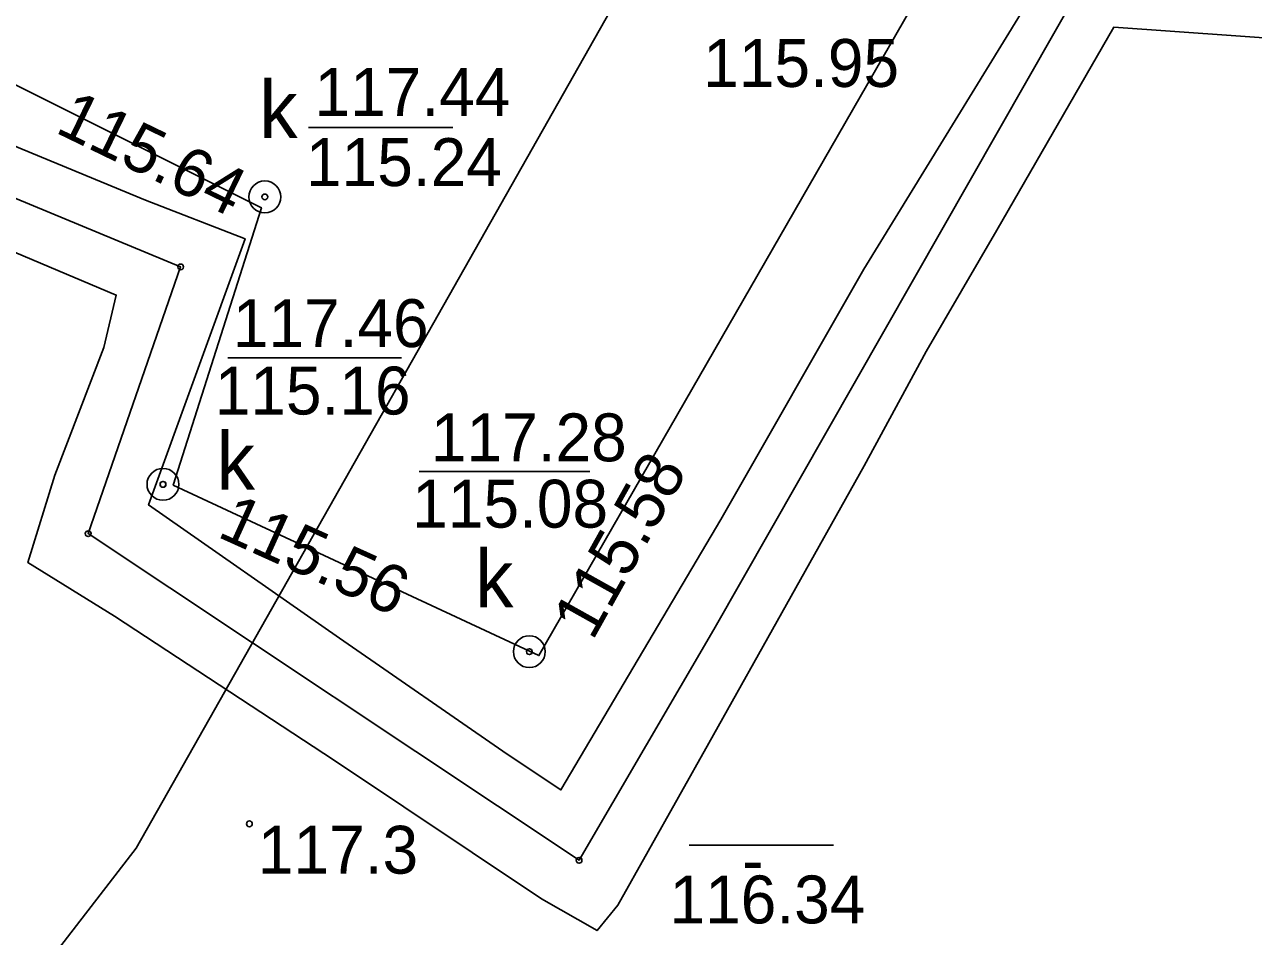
# Model space of a CAD drawing. Extents: x 6434771 to 6436222, y 5663454 to 5664782.
# Drawn here: x 6435606.44 to 6435625.69, y 5663645.64 to 5663659.92 of the extents above; entities that cross this region are included whole.
import ezdxf

# ---------------------------------------------------------------- set-up
doc = ezdxf.new("R2010")
doc.units = 0
for name, color, linetype in [('Warstwa 12', 7, 'Continuous'), ('Warstwa 13', 7, 'Continuous'), ('Warstwa 14', 7, 'Continuous'), ('Warstwa 4', 7, 'Continuous'), ('Warstwa 5', 7, 'Continuous'), ('Warstwa 6', 7, 'Continuous'), ('Warstwa 7', 7, 'Continuous'), ('Warstwa 8', 7, 'Continuous')]:
    doc.layers.add(name, color=color, linetype=linetype)

msp = doc.modelspace()

# ---------------------------------------------------------------- linework, layer by layer
at = {"layer": 'Warstwa 12'}
for points in [[(6435536.288, 5663690.931), (6435537.172, 5663690.476), (6435546.174, 5663686.087), (6435560.885, 5663678.992), (6435558.328, 5663673.766), (6435568.133, 5663668.92), (6435571.279, 5663674.37), (6435579.356, 5663669.847), (6435581.411, 5663668.891), (6435583.323, 5663667.758), (6435587.841, 5663665.584), (6435593.727, 5663662.778), (6435599.053, 5663660.202), (6435608.884, 5663656.122), (6435607.435, 5663651.945), (6435615.124, 5663646.829), (6435617.232, 5663650.442), (6435623.025, 5663660.599), (6435627.209, 5663660.193), (6435635.46, 5663657.931), (6435659.136, 5663652.875), (6435674.047, 5663650.076)], [(6435616.649, 5663663.165), (6435616.261, 5663661.285), (6435608.187, 5663647.021), (6435597.641, 5663633.357), (6435587.173, 5663617.963), (6435578.019, 5663605.151)]]:
    msp.add_lwpolyline(points, dxfattribs=at)
at = {"layer": 'Warstwa 13'}
msp.add_circle((6435609.96, 5663647.4), 0.045, dxfattribs=at)
at = {"layer": 'Warstwa 14'}
for p, q in [((6435613.148, 5663658.307), (6435610.887, 5663658.307)), ((6435612.343, 5663654.7), (6435609.621, 5663654.7)), ((6435615.292, 5663652.919), (6435612.618, 5663652.919)), ((6435616.847, 5663647.064), (6435619.108, 5663647.064))]:
    msp.add_line(p, q, dxfattribs=at)
for centre in [(6435610.202, 5663657.218), (6435610.202, 5663657.218), (6435608.884, 5663656.122), (6435608.607, 5663652.717), (6435608.607, 5663652.717), (6435607.435, 5663651.945), (6435614.345, 5663650.097), (6435614.345, 5663650.097), (6435615.124, 5663646.829)]:
    msp.add_circle(centre, 0.045, dxfattribs=at)
at = {"layer": 'Warstwa 4'}
for centre in [(6435610.202, 5663657.218), (6435608.607, 5663652.717), (6435614.345, 5663650.097)]:
    msp.add_circle(centre, 0.25, dxfattribs=at)
at = {"layer": 'Warstwa 6'}
for centre in [(6435610.202, 5663657.218), (6435608.608, 5663652.717), (6435614.345, 5663650.097)]:
    msp.add_circle(centre, 0.045, dxfattribs=at)
at = {"layer": 'Warstwa 7'}
msp.add_lwpolyline([(6435540.167, 5663690.884), (6435541.124, 5663690.377), (6435544.265, 5663688.814), (6435546.367, 5663687.814), (6435549.985, 5663686.018), (6435562.681, 5663679.846), (6435560.894, 5663675.405), (6435560.702, 5663674.884), (6435561.582, 5663674.343), (6435567.305, 5663671.224), (6435570.385, 5663675.979), (6435580.705, 5663670.944), (6435582.226, 5663671.016), (6435610.149, 5663657.048), (6435608.767, 5663652.705), (6435614.495, 5663650.035), (6435622.045, 5663663.165), (6435674.066, 5663651.59)], dxfattribs=at)
at = {"layer": 'Warstwa 8'}
for points in [[(6435656.566, 5663654.213), (6435647.25, 5663656.205), (6435645.205, 5663656.594), (6435644.134, 5663656.822), (6435643.238, 5663657.068), (6435641.725, 5663657.379), (6435626.709, 5663661.039), (6435622.75, 5663661.251), (6435619.582, 5663656.089), (6435617.344, 5663652.166), (6435614.839, 5663647.931), (6435614, 5663648.491), (6435611.371, 5663650.309), (6435608.383, 5663652.395), (6435609.893, 5663656.564), (6435608.331, 5663657.168), (6435603.468, 5663659.178)], [(6435601.266, 5663658.475), (6435607.876, 5663655.681), (6435607.683, 5663654.861), (6435606.915, 5663652.862), (6435606.488, 5663651.495), (6435607.849, 5663650.651), (6435611.291, 5663648.394), (6435614.537, 5663646.225), (6435615.407, 5663645.729), (6435615.732, 5663646.125), (6435617.157, 5663648.666), (6435619.59, 5663653.009), (6435620.56, 5663654.798), (6435621.665, 5663656.7), (6435623.498, 5663659.876), (6435626.363, 5663659.673), (6435627.759, 5663659.336), (6435648.28, 5663654.422), (6435657.33, 5663652.483)]]:
    msp.add_lwpolyline(points, dxfattribs=at)

# ---------------------------------------------------------------- texts
at = {"layer": 'Warstwa 13'}
msp.add_text('117.3', height=0.75, dxfattribs=at).set_placement((6435610.094, 5663646.62))
at = {"layer": 'Warstwa 14'}
for s, p in [('115.95', (6435617.068, 5663658.941)), ('115.24', (6435610.847, 5663657.389)), ('115.16', (6435609.417, 5663653.811)), ('115.08', (6435612.511, 5663652.039)), ('-', (6435617.676, 5663646.461)), ('116.34', (6435616.54, 5663645.841))]:
    msp.add_text(s, height=0.75, dxfattribs=at).set_placement(p)
for s, rotation, p in [('115.64', 334.1146, (6435606.899, 5663658.238)), ('115.58', 60.7966, (6435615.333, 5663650.252)), ('115.56', 335.7074, (6435609.437, 5663651.905))]:
    msp.add_text(s, height=0.75, rotation=rotation, dxfattribs=at).set_placement(p)
at = {"layer": 'Warstwa 5'}
for p in [(6435610.115, 5663658.14), (6435609.446, 5663652.634), (6435613.494, 5663650.791)]:
    msp.add_text('k', height=0.9, dxfattribs=at).set_placement(p)
at = {"layer": 'Warstwa 6'}
for s, p in [('117.44', (6435610.98, 5663658.487)), ('117.46', (6435609.7, 5663654.867)), ('117.28', (6435612.803, 5663653.078))]:
    msp.add_text(s, height=0.75, dxfattribs=at).set_placement(p)

doc.saveas('drawing.dxf')
